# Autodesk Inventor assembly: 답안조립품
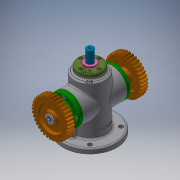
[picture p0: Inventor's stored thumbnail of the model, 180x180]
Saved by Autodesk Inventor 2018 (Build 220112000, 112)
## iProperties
Created: 2020-06
Part Number: 답안조립품
Material: 일반
Document SubType Name: Assembly
Designer: USER
Mass: 1364.2 g
Surface Area: 1735.34 cm^2
Volume: 520.94 cm^3
Density: 2.61874 g/cm^3
Author: USER
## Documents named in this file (17)
- C:\Users\USER\Desktop\600606V1018\답안조립품.iam
- C:\Users\USER\Desktop\600606V1018\가변스프링.ipt
- C:\Users\USER\Desktop\600606V1018\멈춤링.ipt
- C:\Users\USER\Desktop\600606V1018\베어링 6203.ipt
- C:\Users\USER\Desktop\600606V1018\본체.ipt
- C:\Users\USER\Desktop\600606V1018\볼트 M4.ipt
- C:\Users\USER\Desktop\600606V1018\부시.ipt
- C:\Users\USER\Desktop\600606V1018\스퍼기어.ipt
- C:\Users\USER\Desktop\600606V1018\스프링와셔.ipt
- C:\Users\USER\Desktop\600606V1018\스프링조립용 와셔.ipt
- C:\Users\USER\Desktop\600606V1018\슬라이더.ipt
- C:\Users\USER\Desktop\600606V1018\오일 실 17 30 8.ipt
- C:\Users\USER\Desktop\600606V1018\커버 A.ipt
- C:\Users\USER\Desktop\600606V1018\커버 B.ipt
- C:\Users\USER\Desktop\600606V1018\키 4x4x12.ipt
- C:\Users\USER\Desktop\600606V1018\편심축.ipt
- C:\Users\USER\Desktop\600606V1018\평와셔.ipt
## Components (1 placed, 1 different names)
1. 가변스프링:1
